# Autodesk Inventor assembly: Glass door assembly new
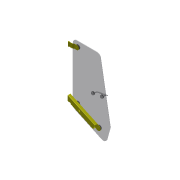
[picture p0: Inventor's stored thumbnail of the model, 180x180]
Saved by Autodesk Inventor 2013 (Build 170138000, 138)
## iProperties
Shininess: 64.0
Length Units: 11269
Angle Units: 11279
Time Units: 11290
Mass Units: 11283
Length Display Precision: 3
Angle Display Precision: 2
Compacted: True
Created: 2005-02
Part Number: Glass door assembly new
Document SubType Name: Assembly
Designer: =<Author>
Manufacturer: Standard
Standards Organization: Custom
Description: =<Part Number>
Mass: 10535.8 g
Surface Area: 16971.1 cm^2
Volume: 5677.68 cm^3
Density: 1.85565 g/cm^3
Density: 0.0
Volumn: 0.0
Area: 0.0
PropertySet Name: Model Information
Control State: 0
Master: False
Checked Out: False
Checked Out Date: 2008-10-15
Last Check In Date: 2008-10-15
Author: PVitaliy
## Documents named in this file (10)
- D:\_Workspace\Dropbox\Launch 2013\LaunchFolder\Dataset\Front Loader\Data\Assy, Cab\Glass door assembly new.iam
- D:\_Workspace\Dropbox\Launch 2013\LaunchFolder\Dataset\Front Loader\Data\Assy, Cab\Glass door.ipt
- D:\_Workspace\Dropbox\Launch 2013\LaunchFolder\Dataset\Front Loader\Data\Assy, Cab\glass hinge.iam
- D:\_Workspace\Dropbox\Launch 2013\LaunchFolder\Dataset\Front Loader\Data\Assy, Cab\rubber ring.ipt
- D:\_Workspace\Dropbox\Launch 2013\LaunchFolder\Dataset\Front Loader\Data\Assy, Cab\Large glass hinge.iam
- D:\_Workspace\Dropbox\Launch 2013\LaunchFolder\Dataset\Front Loader\Data\Assy, Cab\PK46.51.13.003.ipt
- D:\_Workspace\Dropbox\Launch 2013\LaunchFolder\Dataset\Front Loader\Data\Assy, Cab\handle on the glass-2.iam
- D:\_Workspace\Dropbox\Launch 2013\LaunchFolder\Dataset\Front Loader\Data\Assy, Cab\PK46.51.13.005.ipt
- D:\_Workspace\Dropbox\Launch 2013\LaunchFolder\Dataset\Front Loader\Data\Assy, Cab\PK46.51.13.040.iam
- D:\_Workspace\Dropbox\Launch 2013\LaunchFolder\Dataset\Front Loader\Data\Assy, Cab\M10-6H.5.019(S16).ipt
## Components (22 placed, 9 different names)
1. glass hinge:1 [sub-assembly] — Insert:1, Angle:1
2. Large glass hinge:1 [sub-assembly] — Insert:2, Insert:3
3. handle on the glass-2:1 [sub-assembly] — Insert:32, Mate:5, Insert:33, Mate:6
4. PK46.51.13.040:1 [sub-assembly] — Insert:30, Mate:1, Mate:2
5. PK46.51.13.040:2 [sub-assembly] — Insert:31, Mate:3, Mate:4
6. Glass door:1 — Insert:4, Insert:5, Insert:6, Insert:7, Insert:8, Angle:1, Insert:9, Insert:26, Insert:27, Insert:28, Insert:29
7. rubber ring:1 — Insert:1, Insert:4
8. rubber ring:2 — Insert:5, Insert:10
9. rubber ring:5 — Insert:9, Insert:12
10. rubber ring:6 — Insert:2, Insert:8
11. rubber ring:3 — Insert:3, Insert:6
12. rubber ring:4 — Insert:7, Insert:11
13. PK46.51.13.003:1 — Insert:10, Insert:23
14. PK46.51.13.003:2 — Insert:12, Insert:25
15. PK46.51.13.003:3 — Insert:11, Insert:24
16. PK46.51.13.005:1 — Insert:26, Mate:4, Insert:32, Mate:5
17. PK46.51.13.005:2 — Insert:28, Mate:2, Insert:33, Mate:6
18. PK46.51.13.005:3 — Insert:29, Insert:31, Mate:3
19. PK46.51.13.005:4 — Insert:27, Insert:30, Mate:1
20. M10-6H.5.019(S16):1 — Insert:23
21. M10-6H.5.019(S16):2 — Insert:24
22. M10-6H.5.019(S16):3 — Insert:25
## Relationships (30: Insert 23, Mate 6, Angle 1)
- Insert:1: glass hinge:1 ↔ rubber ring:1
- Insert:2: Large glass hinge:1 ↔ rubber ring:6
- Insert:3: Large glass hinge:1 ↔ rubber ring:3
- Insert:4: Glass door:1 ↔ rubber ring:1
- Insert:5: Glass door:1 ↔ rubber ring:2
- Insert:6: Glass door:1 ↔ rubber ring:3
- Insert:7: Glass door:1 ↔ rubber ring:4
- Insert:8: Glass door:1 ↔ rubber ring:6
- Angle:1: glass hinge:1 ↔ Glass door:1
- Insert:9: Glass door:1 ↔ rubber ring:5
- Insert:10: rubber ring:2 ↔ PK46.51.13.003:1
- Insert:11: rubber ring:4 ↔ PK46.51.13.003:3
- Insert:12: rubber ring:5 ↔ PK46.51.13.003:2
- Insert:23: PK46.51.13.003:1 ↔ M10-6H.5.019(S16):1
- Insert:24: PK46.51.13.003:3 ↔ M10-6H.5.019(S16):2
- Insert:25: PK46.51.13.003:2 ↔ M10-6H.5.019(S16):3
- Insert:26: Glass door:1 ↔ PK46.51.13.005:1
- Insert:27: Glass door:1 ↔ PK46.51.13.005:4
- Insert:28: Glass door:1 ↔ PK46.51.13.005:2
- Insert:29: Glass door:1 ↔ PK46.51.13.005:3
- Insert:30: PK46.51.13.040:1 ↔ PK46.51.13.005:4
- Mate:1: PK46.51.13.040:1 ↔ PK46.51.13.005:4
- Mate:2: PK46.51.13.040:1 ↔ PK46.51.13.005:2
- Insert:31: PK46.51.13.040:2 ↔ PK46.51.13.005:3
- Mate:3: PK46.51.13.040:2 ↔ PK46.51.13.005:3
- Mate:4: PK46.51.13.040:2 ↔ PK46.51.13.005:1
- Insert:32: handle on the glass-2:1 ↔ PK46.51.13.005:1
- Mate:5: handle on the glass-2:1 ↔ PK46.51.13.005:1
- Insert:33: handle on the glass-2:1 ↔ PK46.51.13.005:2
- Mate:6: handle on the glass-2:1 ↔ PK46.51.13.005:2
